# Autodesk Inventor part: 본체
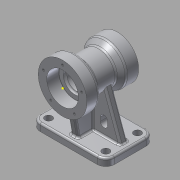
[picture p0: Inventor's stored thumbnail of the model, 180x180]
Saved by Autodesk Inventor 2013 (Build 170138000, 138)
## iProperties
Created: 2015-08
Part Number: 본체
Material: 알루미늄 6061
Document SubType Name: Modeling
Designer: ST4
Density: 2.71 g/cm^3
Mass: 1055 g
Surface Area: 768.882 cm^2
Volume: 389.298 cm^3
Author: ST4
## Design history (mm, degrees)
sketch "스케치1"
  geometry: 1 further point
sketch "스케치2"
  geometry: L1 (0, 0)-(90, 0); L2 (0, 26)-(0, 40); L3 (0, 40)-(20, 40); L4 (20, 40)-(27.506, 27); L5 (27.506, 27)-(60.466, 27); L6 (60.466, 27)-(70, 35); L7 (70, 35)-(90, 35); L8 (90, 35)-(90, 20); L9 (90, 20)-(73, 20); L10 (73, 20)-(73, 16); L11 (73, 16)-(23, 16); L12 (23, 16)-(23, 19); L13 (23, 19)-(20, 19); L14 (20, 19)-(20, 26); L15 (20, 26)-(0, 26)
  constraints: 30 end point, 8 parallel, 4 perpendicular, 1 horizontal
  dimensions: "d0" = 90 distance of L1.start L1.end; "d2" = 32 diameter of L11 L1; "d3" = 38 diameter of L13 L1; "d4" = 52 diameter of L15 L1; "d5" = 40 diameter of L9 L1; "d6" = 17 distance between parallel lines of L8 L10; "d7" = 20 distance between parallel lines of L2 L14; "d8" = 3 distance between parallel lines of L14 L12; "d9" = 0 distance from line of L1.start L2; "d10" = 90 distance between parallel lines of L2 L8; "d11" = 20 distance from line of L2 L3.end; "d12" = 20 distance of L7.end L6.end; "d13" = 40 deg angle of L7 L6; "d14" = 60 deg angle of L3 L4; "d15" = 80 diameter of L3 L1; "d16" = 70 diameter of L7 L1; "d17" = 54 diameter of L5 L1
revolve "회전1" sketch "스케치2" stored, may be unused: angle "d18" = 90 deg
node "작업 평면1"
sketch "스케치3"
  geometry: L1 (-61, 90)-(61, 90); L2 (61, 90)-(61, 10); L3 (61, 10)-(-61, 10); L4 (-61, 10)-(-61, 90); L5 (20, 90)-(-20, 90) reference; 1 further point
  constraints: 8 end point, 2 parallel, 1 horizontal, 1 perpendicular
  dimensions: "d21" = 80 distance between parallel lines of L3 L1; "d22" = 122 distance between parallel lines of L2 L4; "d23" = 61 distance from line of point (0, 0) L4; "d24" = 0 distance between parallel lines of L5 L1
extrude "돌출1" join sketch "스케치3" distance "d25" = 12; taper "d26" = 0 deg
fillet "모깎기1" dims "d27" = 14
sketch "스케치4"
  geometry: C1 r 6 at (-47, 76); C2 r 6 at (47, 76); C3 r 6 at (47, 24); C4 r 6 at (-47, 24); A1 r 14 centre (-47, 76) between (-47, 90) and (-61, 76) reference; A2 r 14 centre (-47, 24) between (-61, 24) and (-47, 10) reference; A3 r 14 centre (47, 24) between (47, 10) and (61, 24) reference; A4 r 14 centre (47, 76) between (61, 76) and (47, 90) reference; 1 further point
  constraints: 4 centre point, 4 coincident
  dimensions: "d28" = 12 diameter of C1; "d30" = 12 diameter of C4; "d31" = 12 diameter of C3; "d32" = 12 diameter of C2
extrude "돌출2" cut sketch "스케치4" stored distance "d33" = 12; taper "d34" = 0 deg
node "작업 평면2"
fillet "모깎기3" dims "d73" = 0.3
fillet "모깎기4" dims "d74" = 5
sketch "스케치8"
  geometry: L1 (0, -40)-(17.113, -40) reference; L2 (21.443, -37.5)-(26.062, -29.5) reference; L3 (30.392, -27)-(58.646, -27) reference; L4 (61.86, -28.17)-(68.606, -33.83) reference; L5 (71.82, -35)-(90, -35) reference; L6 (76, -78)-(24, -78) reference; L7 (10, -78)-(24, -78) reference; L8 (70, -78)-(82, -78) reference; L9 (76, -78)-(90, -78) reference; L10 (13.3, -40)-(20, -78); L11 (80, -35)-(80, -78); L12 (10, -90)-(10, -78) reference; A1 r 5 centre (17.113, -35) between (17.113, -40) and (21.443, -37.5) reference; A2 r 5 centre (30.392, -32) between (30.392, -27) and (26.062, -29.5) reference; A3 r 5 centre (58.646, -32) between (61.86, -28.17) and (58.646, -27) reference; A4 r 5 centre (71.82, -30) between (68.606, -33.83) and (71.82, -35) reference; 1 further point
  constraints: 4 end point, 4 point on line, 1 perpendicular
  dimensions: "d75" = 80 deg angle of L7 L10; "d76" = 10 distance from line of L12 L10.end; "d77" = 10 distance from line of L9.end L11
extrude "돌출6" join sketch "스케치8" stored distance "d78" = 12; taper "d79" = 0 deg
sketch "스케치9"
  geometry: L1 (94, 12)-(0, 12) reference; L2 (-14, 12)-(0, 12) reference; L3 (88, 12)-(100, 12) reference; L4 (94, 12)-(108, 12) reference; L5 (21.336, 81.611)-(-4, 12); L6 (72.664, 81.611)-(98, 12); L7 (-14, 0)-(-14, 12) reference; L8 (108, 12)-(108, 0) reference; L9 (0, 12)-(0, 0) reference; L10 (94, 12)-(0, 12) reference; L11 (94, 0)-(94, 12) reference; L12 (0, 0)-(94, 0) reference; L13 (6, 0)-(-6, 0) reference; L14 (-6, 12)-(6, 12) reference; L15 (-14, 12)-(0, 12) reference; L16 (0, 12)-(0, 0) reference; L17 (0, 0)-(-14, 0) reference; L18 (-14, 0)-(-14, 12) reference; L19 (100, 0)-(88, 0) reference; L20 (88, 12)-(100, 12) reference; L21 (94, 12)-(108, 12) reference; L22 (108, 12)-(108, 0) reference; L23 (108, 0)-(94, 0) reference; L24 (94, 0)-(94, 12) reference; L25 (-4, 12)-(98, 12); A1 r 27 centre (47, 90) between (47, 63) and (21.336, 81.611) reference; 1 further point
  constraints: 6 end point, 2 point on circle, 2 point on line, 1 collinear
  dimensions: "d80" = 70 deg angle of L1 L5; "d81" = 70 deg angle of L1 L6; "d82" = 10 distance from line of L7 L5.end; "d83" = 10 distance from line of L8 L6.end
extrude "돌출7" join sketch "스케치9" stored distance "d84" = 12; taper "d85" = 0 deg
sketch "스케치10" dims "d86" = 66
  geometry: C1 r 40 at (0, 0) reference; C2 r 26 at (0, 0) reference; 2 further points
  constraints: 1 coincident, 1 vertical alignment, 2 other
  dimensions: "d89" = 0 horizontal distance of C1.centre point (0, 33)
hole "구멍1" sketch "스케치10" at (0, 33) diameter "d90" = 3.459; stored, may be unused: countersink angle "d94" = 90 deg, drill point angle "d96" = 118 deg; dims "d91" = 10, "d92" = 4, "d93" = 2, "d95" = 13
sketch "스케치11" dims "d100" = 54
  geometry: C1 r 20 at (0, 0) reference; C2 r 35 at (0, 0) reference; 2 further points
  constraints: 1 coincident, 1 vertical alignment, 2 other
  dimensions: "d102" = 0 horizontal distance of C1.centre point (0, -27)
hole "구멍2" sketch "스케치11" at (0, -27) diameter "d103" = 3.459; stored, may be unused: countersink angle "d107" = 90 deg, drill point angle "d109" = 118 deg; dims "d104" = 10, "d105" = 4, "d106" = 2, "d108" = 13
fillet "모깎기5" dims "d113" = 3
fillet "모깎기6" dims "d114" = 3
fillet "모깎기7" dims "d115" = 3
fillet "모깎기8" dims "d116" = 3
sketch "스케치12"
  geometry: L1 (38, 63)-(38, 15) reference; L2 (17, 36)-(17, 30); L3 (29, 36)-(29, 30); L4 (94, 12)-(0, 12) reference; A1 r 27 centre (47, 90) between (23.047, 77.54) and (47, 63) reference; A2 r 6 centre (23, 36) between (29, 36) and (17, 36); A3 r 6 centre (23, 30) between (17, 30) and (29, 30)
  constraints: 4 end point, 4 point on circle, 2 centre point, 2 parallel, 2 tangent
  dimensions: "d117" = 0 horizontal distance of A3.centre A2.centre; "d119" = 6 distance of A3.centre A2.centre; "d122" = 6 radius of A2; "d123" = 6 radius of A3; "d124" = 18 distance from line of L4 A3.centre; "d125" = 24 horizontal distance of A1.centre A3.centre
extrude "돌출8" cut sketch "스케치12" stored distance "d126" = 12; taper "d127" = 0 deg
fillet "모깎기9" dims "d128" = 3
sketch "스케치13"
  geometry: L1 (-78, 87)-(-78, 76) reference; L2 (-35, 80)-(-75, 80) reference; L3 (-74.739, 67.002)-(-33.261, 67.002); L4 (-33.261, 67.002)-(-33.261, 60.998); L5 (-33.261, 60.998)-(-74.739, 60.998); L6 (-74.739, 60.998)-(-74.739, 67.002); L7 (-33.261, 64)-(-74.739, 64); L8 (-54, 67.002)-(-54, 60.998); 1 further point
  constraints: 4 end point, 4 midpoint, 2 other
  dimensions: "d134" = 24 distance between parallel lines of L1 L8; "d135" = 16 distance between parallel lines of L2 L7
extrude "돌출9" join sketch "스케치13" distance "d136" = 0.5; taper "d137" = 0 deg
node "솔리드1"
pattern_circular "원형 패턴1" dims angle "d98" = 360 deg
pattern_circular "원형 패턴2" dims angle "d111" = 360 deg
mirror "대칭2"
node "투영된 루프2"
node "투영된 루프3"
node "투영된 루프4"
node "투영된 루프5"
node "투영된 루프6"
other parameters: "d54" = 12, "d56" = 12, "d61" = 12, "d62" = 12, "d120" = 12, "d121" = 12
